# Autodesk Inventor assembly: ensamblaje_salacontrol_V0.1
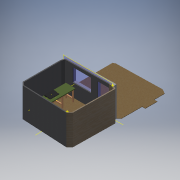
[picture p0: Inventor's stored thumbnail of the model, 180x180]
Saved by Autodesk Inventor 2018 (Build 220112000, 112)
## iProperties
Created: 2018-07
Part Number: ensamblaje_salacontrol_V0.1
Document SubType Name: Assembly
Designer: Gordillo
Author: Gordillo
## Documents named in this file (5)
- D:\ownCloud\SmartOpenLab\Documentos\Planos\EspacioAudioSalaControl\ensamblaje_salacontrol_V0.1.iam
- D:\ownCloud\SmartOpenLab\Documentos\Planos\EspacioAudioSalaControl\mesa_salacontrol_V0.1.ipt
- D:\ownCloud\SmartOpenLab\Documentos\Planos\EspacioAudioSalaControl\mesa_mezclas_V0.1.ipt
- D:\ownCloud\SmartOpenLab\Documentos\Planos\EspacioAudioSalaControl\tarima_base_V0..2.ipt
- D:\ownCloud\SmartOpenLab\Documentos\Planos\EspacioAudioSalaControl\sala_grabacion_V0.1.ipt
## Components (4 placed, 4 different names)
1. tarima_base_V0..2:1 — Flush:1, Flush:2
2. mesa_salacontrol_V0.1:1
3. mesa_mezclas_V0.1:1
4. sala_grabacion_V0.1:1 — Flush:1, Flush:2
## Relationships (2: Flush 2)
- Flush:1: tarima_base_V0..2:1 ↔ sala_grabacion_V0.1:1
- Flush:2: tarima_base_V0..2:1 ↔ sala_grabacion_V0.1:1
